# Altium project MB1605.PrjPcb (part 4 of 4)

## Sheet ETHERNET.SchDoc: ETHERNET
size A3; Date: Not used; ApprovedBy: Not used; CheckedBy: Not used; Author: Not used; CompanyName: STMicroelectronics; DrawnBy: Not used; Engineer: Not used; Organization: Not used; Address1: Not used; Address2: Not used; Address3: Not used; Address4: Not used; DocumentNumber: Not used; Revision: Not used; SheetNumber: 8; SheetTotal: 18
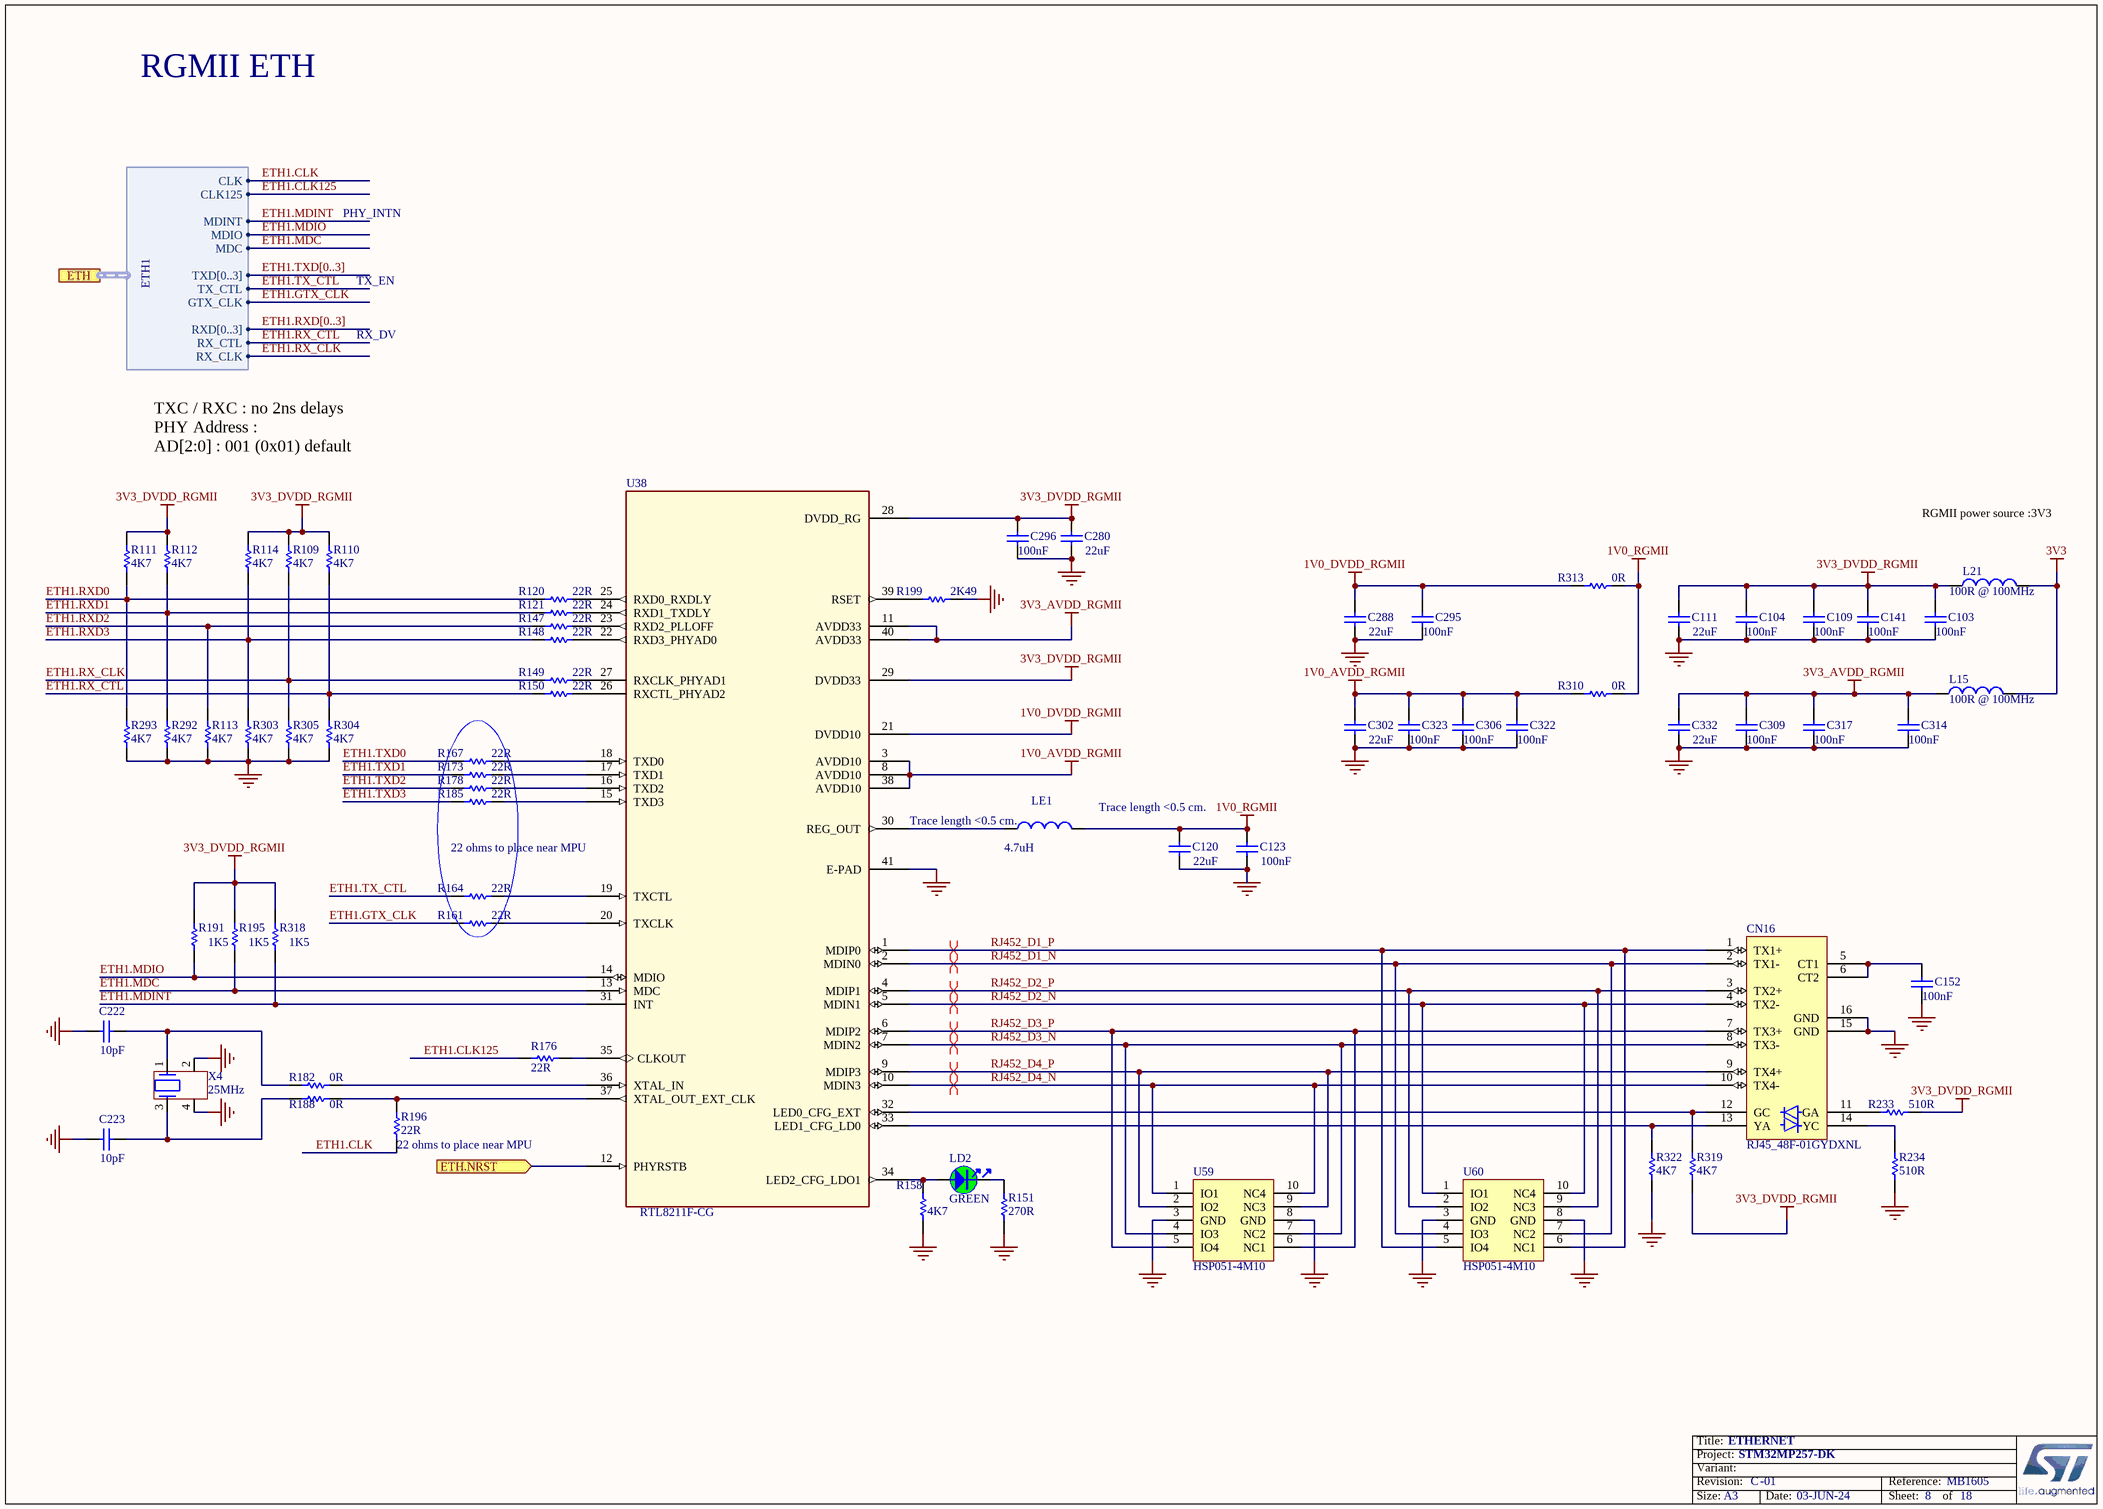
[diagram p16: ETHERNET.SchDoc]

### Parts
C103  value 100nF  [C0402]
C104  value 100nF  [C0402]
C109  value 100nF  [C0402]
C111  value 22uF  [C0603]
C120  value 22uF  [C0603]
C123  value 100nF  [C0402]
C141  value 100nF  [C0402]
C152  value 100nF  [C0402]
C222  value 10pF  [C0402]
C223  value 10pF  [C0402]
C280  value 22uF  [C0603]
C288  value 22uF  [C0603]
C295  value 100nF  [C0402]
C296  value 100nF  [C0402]
C302  value 22uF  [C0603]
C306  value 100nF  [C0402]
C309  value 100nF  [C0402]
C314  value 100nF  [C0402]
C317  value 100nF  [C0402]
C322  value 100nF  [C0402]
C323  value 100nF  [C0402]
C332  value 22uF  [C0603]
CN16  value RJ45_48F-01GYDXNL  [CON_RJ45_YD_48F-01GYDXNL_LED-P]  (hidden comment: ​New part for use of led pulled down on pin 13/14 , schematic more lisible.)
L15  value 100R @ 100MHz  [FIL_0603_H0P65]
L21  value 100R @ 100MHz  [FIL_0603_H0P65]
LD2  value GREEN  [LED_0603_OSRAM_LG-Q396-PS-35_GREEN_1A2K_H0P4]  (hidden comment: LED_green)
LE1  value 4.7uH  [L1210_LQH]
R109  value 4K7  [R0402]
R110  value 4K7  [R0402]
R111  value 4K7  [R0402]
R112  value 4K7  [R0402]
R113  value 4K7  [R0402]
R114  value 4K7  [R0402]
R120  value 22R  [R0201_H0P23]  (hidden comment: Resistor)
R121  value 22R  [R0201_H0P23]  (hidden comment: Resistor)
R147  value 22R  [R0201_H0P23]  (hidden comment: Resistor)
R148  value 22R  [R0201_H0P23]  (hidden comment: Resistor)
R149  value 22R  [R0201_H0P23]  (hidden comment: Resistor)
R150  value 22R  [R0201_H0P23]  (hidden comment: Resistor)
R151  value 270R  [R0402]  (hidden comment: Resistor)
R158  value 4K7  [R0402]
R161  value 22R  [R0201_H0P23]  (hidden comment: Resistor)
R164  value 22R  [R0201_H0P23]  (hidden comment: Resistor)
R167  value 22R  [R0201_H0P23]  (hidden comment: Resistor)
R173  value 22R  [R0201_H0P23]  (hidden comment: Resistor)
R176  value 22R  [R0201_H0P23]  (hidden comment: Resistor)
R178  value 22R  [R0201_H0P23]  (hidden comment: Resistor)
R182  value 0R  [R0402]
R185  value 22R  [R0201_H0P23]  (hidden comment: Resistor)
R188  value 0R  [R0402]
R191  value 1K5  [R0402]
R195  value 1K5  [R0402]
R196  value 22R  [R0201_H0P23]  (hidden comment: Resistor)
R199  value 2K49  [R0402]
R233  value 510R  [R0402]
R234  value 510R  [R0402]
R292  value 4K7  [R0402]
R293  value 4K7  [R0402]
R303  value 4K7  [R0402]
R304  value 4K7  [R0402]
R305  value 4K7  [R0402]
R310  value 0R  [R0603]
R313  value 0R  [R0603]
R318  value 1K5  [R0402]
R319  value 4K7  [R0402]
R322  value 4K7  [R0402]
U38  RTL8211F-CG  [ICC_QFN40-EPAD_5X5_P040]
U59  HSP051-4M10  [ESD_UQFN-10L_2P5X1_P050]
U60  HSP051-4M10  [ESD_UQFN-10L_2P5X1_P050]
X4  value 25MHz  [CRY_NX3225HA_4P]  (hidden comment: XTAL_4_PINS)

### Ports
ETH (harness ETH1), ETH.NRST (in)

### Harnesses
ETH1: MDINT, CLK125, TXD[0..3], MDIO, MDC, RX_CLK, GTX_CLK, TX_CTL, RXD[0..3], RX_CTL, CLK

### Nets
1V0_AVDD_RGMII: C302.2 C306.2 C322.2 C323.2 R310.1 U38.3(AVDD10) U38.8(AVDD10) U38.38(AVDD10)
1V0_DVDD_RGMII: C288.2 C295.2 R313.1 U38.21(DVDD10)
1V0_RGMII: C120.2 C123.2 LE1.2 R310.2 R313.2
3V3: L15.2 L21.2
3V3_AVDD_RGMII: C309.2 C314.2 C317.2 C332.2 L15.1 U38.11(AVDD33) U38.40(AVDD33)
3V3_DVDD_RGMII: C103.2 C104.2 C109.2 C111.2 C141.2 C280.1 C296.2 L21.1 R109.2 R110.2 R111.2 R112.2 R114.2 R191.2 R195.2 R233.2 R318.2 R319.1 U38.28(DVDD_RG) U38.29(DVDD33)
GND: C103.1 C104.1 C109.1 C111.1 C120.1 C123.1 C141.1 C152.1 C222.1 C223.1 C280.2 C288.1 C295.1 C296.1 C302.1 C306.1 C309.1 C314.1 C317.1 C322.1 C323.1 C332.1 CN16.15(GND) CN16.16(GND) R113.1 R151.2 R158.1 R199.2 R234.1 R292.1 R293.1 R303.1 R304.1 R305.1 R322.1 U38.41(E-PAD) U59.3(GND) U59.8(GND) U60.3(GND) U60.8(GND) X4.2 X4.4
ETH1.CLK: R196.1 ; port ETH.CLK
ETH1.CLK125: R176.1 ; port ETH.CLK125
ETH1.GTX_CLK: R161.1 ; port ETH.GTX_CLK
ETH1.MDC: R195.1 U38.13(MDC) ; port ETH.MDC
ETH1.MDINT: R318.1 U38.31(INT) ; port ETH.MDINT
ETH1.MDIO: R191.1 U38.14(MDIO) ; port ETH.MDIO
ETH1.NRST: U38.12(PHYRSTB) ; port ETH.NRST
ETH1.RX_CLK: R109.1 R149.1 R305.2 ; port ETH.RX_CLK
ETH1.RX_CTL: R110.1 R150.1 R304.2 ; port ETH.RX_CTL
ETH1.RXD0: R111.1 R120.1 R293.2
ETH1.RXD1: R112.1 R121.1 R292.2
ETH1.RXD2: R113.2 R147.1
ETH1.RXD3: R114.1 R148.1 R303.2
ETH1.TX_CTL: R164.1 ; port ETH.TX_CTL
ETH1.TXD0: R167.1
ETH1.TXD1: R173.1
ETH1.TXD2: R178.1
ETH1.TXD3: R185.1
RJ452_D1_N: CN16.2(TX1-) U38.2(MDIN0) U60.4(IO3) U60.7(NC2)
RJ452_D1_P: CN16.1(TX1+) U38.1(MDIP0) U60.5(IO4) U60.6(NC1)
RJ452_D2_N: CN16.4(TX2-) U38.5(MDIN1) U60.1(IO1) U60.10(NC4)
RJ452_D2_P: CN16.3(TX2+) U38.4(MDIP1) U60.2(IO2) U60.9(NC3)
RJ452_D3_N: CN16.8(TX3-) U38.7(MDIN2) U59.4(IO3) U59.7(NC2)
RJ452_D3_P: CN16.7(TX3+) U38.6(MDIP2) U59.5(IO4) U59.6(NC1)
RJ452_D4_N: CN16.10(TX4-) U38.10(MDIN3) U59.1(IO1) U59.10(NC4)
RJ452_D4_P: CN16.9(TX4+) U38.9(MDIP3) U59.2(IO2) U59.9(NC3)
NetC152_2: C152.2 CN16.5(CT1) CN16.6(CT2)
NetC222_2: C222.2 R182.1 X4.1
NetC223_2: C223.2 R188.1 X4.3
NetCN16_11: CN16.11(GA) R233.1
NetCN16_12: CN16.12(GC) R319.2 U38.32(LED0_CFG_EXT)
NetCN16_13: CN16.13(YA) R322.2 U38.33(LED1_CFG_LD0)
NetCN16_14: CN16.14(YC) R234.2
NetLD2_1: LD2.1 R158.2 U38.34(LED2_CFG_LDO1)
NetLD2_2: LD2.2 R151.1
NetLE1_1: LE1.1 U38.30(REG_OUT)
NetR120_2: R120.2 U38.25(RXD0_RXDLY)
NetR121_2: R121.2 U38.24(RXD1_TXDLY)
NetR147_2: R147.2 U38.23(RXD2_PLLOFF)
NetR148_2: R148.2 U38.22(RXD3_PHYAD0)
NetR149_2: R149.2 U38.27(RXCLK_PHYAD1)
NetR150_2: R150.2 U38.26(RXCTL_PHYAD2)
NetR161_2: R161.2 U38.20(TXCLK)
NetR164_2: R164.2 U38.19(TXCTL)
NetR167_2: R167.2 U38.18(TXD0)
NetR173_2: R173.2 U38.17(TXD1)
NetR176_2: R176.2 U38.35(CLKOUT)
NetR178_2: R178.2 U38.16(TXD2)
NetR182_2: R182.2 U38.36(XTAL_IN)
NetR185_2: R185.2 U38.15(TXD3)
NetR188_2: R188.2 R196.2 U38.37(XTAL_OUT_EXT_CLK)
NetR199_1: R199.1 U38.39(RSET)

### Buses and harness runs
bus ETH1.RXD[0..3]
bus ETH1.TXD[0..3]

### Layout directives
differential pair: RJ452_D1_N, RJ452_D1_P, RJ452_D2_N, RJ452_D2_P, RJ452_D3_N, RJ452_D3_P, RJ452_D4_N, RJ452_D4_P

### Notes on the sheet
- RGMII ETH
- PHY_INTN
- TX_EN
- RX_DV
- TXC / RXC : no 2ns delays
  PHY Address :
  AD[2:0] : 001 (0x01) default
- RGMII power source :3V3
- (near U38) 22 ohms to place near MPU
- (near LE1) Trace length <0.5 cm.
- Trace length <0.5 cm.
- (near R196) 22 ohms to place near MPU

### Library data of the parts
C103 C104 C109 C123 C141 C152 C295 C296 C306 C309 C314 C317 C322 C323 = MCD-00006: Capacitor,100nF,16V,X7R,10%,0402; Manufacturer_Part_Number: CC0402KRX7R7BB104; Manufacturer: YAGEO; Alternate_Manufacturer: MURATA; Alternate_Manufacturer_Part_Number: GCM155R71C104KA55D; Part_Preference: Recommended; Partial_Alternate_Internal_Part_Number: MCD-03299; Provided_By: SUBCO; Initial_Board_Reference: mb1274; Order_Code_RS: 616-9701; Alternate_EMS: M; Component_Country_Of_Origin: China; ID: 2474; ShowFields: YES
C111 C120 C280 C288 C302 C332 = MCD-00100: Capacitor,22uF,6V3,X5R,20%,0603; Manufacturer_Part_Number: GRM188R60J226MEA0J; Manufacturer: MURATA; Part_Preference: Recommended; ECCN_US: EAR99; ECCN_EU: NEC; Provided_By: SUBCO; Initial_Board_Reference: mb1262; Component_Country_Of_Origin: Japan; ID: 2766; ShowFields: YES
C222 C223 = MCD-00015: Capacitor,10pF,50V,NPO,5%,0402; Manufacturer_Part_Number: CC0402JRNPO9BN100; Manufacturer: YAGEO; Part_Preference: Recommended; Provided_By: SUBCO; Initial_Board_Reference: mb1274; Order_Code_RS: 616-9256; Component_Country_Of_Origin: China; ID: 2465; ShowFields: YES
CN16 = MCD-01129: Connector_RJ45, led pull down, T= 13.84mm; Manufacturer_Part_Number: 48F-01GYDXNL; Manufacturer: YUAN DEAN SCIENTIFIC; Part_Preference: Recommended; Component_Country_Of_Origin: Unknown; ID: 3367; ShowFields: YES
L15 L21 = MCD-00094: Ferrite bead 100R 2A 0603; Manufacturer_Part_Number: BLM18EG101TN1; Manufacturer: MURATA; Part_Type: Inductor; Part_Preference: Recommended; ECCN_US: EAR99; ECCN_EU: NEC; Provided_By: SUBCO; Initial_Board_Reference: mb1262; Order_Code_RS: 792-6246; Component_Country_Of_Origin: Japan; ID: 2774; ShowFields: YES
LD2 = MCD-00588: LED Green, 0603 SMD, Forward Voltage Typ=2V, Max=2.5V; Part_Type: Display; Manufacturer_Part_Number: LG Q396-PS-35; Manufacturer: OSRAM OPTO SEMICONDUCTORS; Alternate_Manufacturer_Part_Number: VLMTG1300-GS08; Alternate_Manufacturer: VISHAY SEMICONDUCTOR OPTO DIVISION; Alternate_Internal_Part_Number: MCD-02400; Part_Preference: Recommended; Provided_By: SUBCO; Component_Country_Of_Origin: Unknown; ID: 3155; ShowFields: YES
LE1 = MCD-00048: FIXED IND 4.7UH 1A 180 MOHM 30% SMD; Manufacturer_Part_Number: LQH32PN4R7NN0L; Manufacturer: MURATA; Part_Preference: Recommended; Provided_By: SUBCO; Initial_Board_Reference: mb1274; Order_Code_RS: 167-4086; Component_Country_Of_Origin: Japan; ID: 2544; ShowFields: YES
R109-R114 R292 R293 R303-R305 = MCD-00065: Resistor,4K7,0402,1%,1/16W; Manufacturer_Part_Number: RC0402FR-074K7L; Manufacturer: YAGEO; Alternate_Manufacturer_Part_Number: RT0402FRE074K7L; Part_Preference: Recommended; Partial_Alternate_Internal_Part_Number: MCD-03300; Provided_By: SUBCO; Initial_Board_Reference: mb1274; Component_Country_Of_Origin: China; ID: 2526; ShowFields: YES; Alternate_EMS: M
R120 R121 R147-R150 R161 R164 R167 R173 R176 R178 R185 R196 = MCD-02978: Resistor, 22R, 0201, +/-1%, 1/20W; Manufacturer_Part_Number: RC0201FR-0722RL; Manufacturer: YAGEO; Part_Preference: Recommended; Order_Code_RS: 198-7593; ID: 5094; ShowFields: YES; Component_Country_Of_Origin: China
R151 = MCD-00441: Resistor,270R,0402,1%,1/16W; Manufacturer_Part_Number: RC0402FR-07270RL; Manufacturer: YAGEO; Part_Preference: Recommended; Provided_By: SUBCO; ECCN_US: EAR99; ECCN_EU: NEC; Component_Country_Of_Origin: China; ID: 2838; ShowFields: YES
R158 R319 R322 = MCD-00065: Resistor,4K7,0402,1%,1/16W; Manufacturer_Part_Number: RC0402FR-074K7L; Manufacturer: YAGEO; Alternate_Manufacturer_Part_Number: RT0402FRE074K7L; Part_Preference: Recommended; Partial_Alternate_Internal_Part_Number: MCD-03300; Provided_By: SUBCO; Initial_Board_Reference: mb1274; Alternate_EMS: M; Component_Country_Of_Origin: China; ID: 2526; ShowFields: YES
R182 R188 = MCD-00052: Resistor,0R,0402,5%,1/16W; Manufacturer_Part_Number: RC0402JR-070RL; Manufacturer: YAGEO; Part_Preference: Recommended; Provided_By: SUBCO; Initial_Board_Reference: mb1274; Order_Code_RS: 618-5804; Component_Country_Of_Origin: China; ID: 2540; ShowFields: YES
R191 R195 R318 = MCD-00068: Resistor,1K5,0402,1%,1/16W; Manufacturer_Part_Number: RC0402FR-071K5L; Manufacturer: YAGEO; Part_Preference: Recommended; Provided_By: SUBCO; Initial_Board_Reference: mb1274; Component_Country_Of_Origin: China; ID: 2524; ShowFields: YES
R199 = MCD-00183: Resistor,2K49,0402,1%,1/16W; Manufacturer_Part_Number: RC0402FR-072K49L; Manufacturer: YAGEO; Part_Preference: Recommended; Provided_By: SUBCO; Component_Country_Of_Origin: China; ID: 2687; ShowFields: YES
R233 R234 = MCD-00064: Resistor,510R,0402,1%,1/16W; Manufacturer_Part_Number: RC0402FR-07510RL; Manufacturer: YAGEO; Part_Preference: Recommended; Provided_By: SUBCO; Initial_Board_Reference: mb1274; Component_Country_Of_Origin: China; ID: 2525; ShowFields: YES
R310 R313 = MCD-00056: Resistor,0R,0603,5%,1/10W; Manufacturer_Part_Number: RC0603JR-070RL; Manufacturer: YAGEO; Part_Preference: Recommended; Provided_By: SUBCO; Initial_Board_Reference: mb1274; Component_Country_Of_Origin: China; ID: 2536; ShowFields: YES
U38 = MCD-01130: 10/100/1000M GIGABIT Ethernet Transceiver, QFN40 , SMPS version; Manufacturer: REALTEK; Part_Type: IC; Part_Preference: Recommended; Provided_By: SUBCO; Initial_Board_Reference: MB1272; Component_Country_Of_Origin: Unknown; ID: 3370; ShowFields: YES
U59 U60 = MCD-00667: 4-line ESD protection for high speed lines; BMS_Part_Number: 9179041; Part_Type: Diode; Part_Preference: Recommended; Manufacturer: STMICROELECTRONICS; Manufacturer_HQ_COO: EU; Component_Country_Of_Origin: Philippines; ShowFields: YES; ID: 3081
X4 = MCD-01463: Crystal 25Mhz, 10pF, -+50PPM, SMD; Part_Type: Crystal_Osc; Manufacturer_Part_Number: NX3225GA-25MHZ-EXS00A-CG06750; Manufacturer: NDK; BMS_Part_Number: 9157035; Part_Preference: Recommended; Provided_By: SUBCO; Initial_Board_Reference: MB1272B; Remark: footprint same as CRY_NX3225HA_4P; Component_Country_Of_Origin: Unknown; ID: 3563; ShowFields: YES

## Sheet HDMI.SchDoc: HDMI
size A3; Date: 01-DEC-2013; CompanyName: STMicroelectronics; Organization: Microcontrollers Division; Address1: 12, Rue Jules HOROWITZ; Address2: 38019 Grenoble; Address3: FRANCE; DocumentNumber: MB1272; Revision: A-01; SheetNumber: 10; SheetTotal: 18; Project: STM32MP25-DISCO
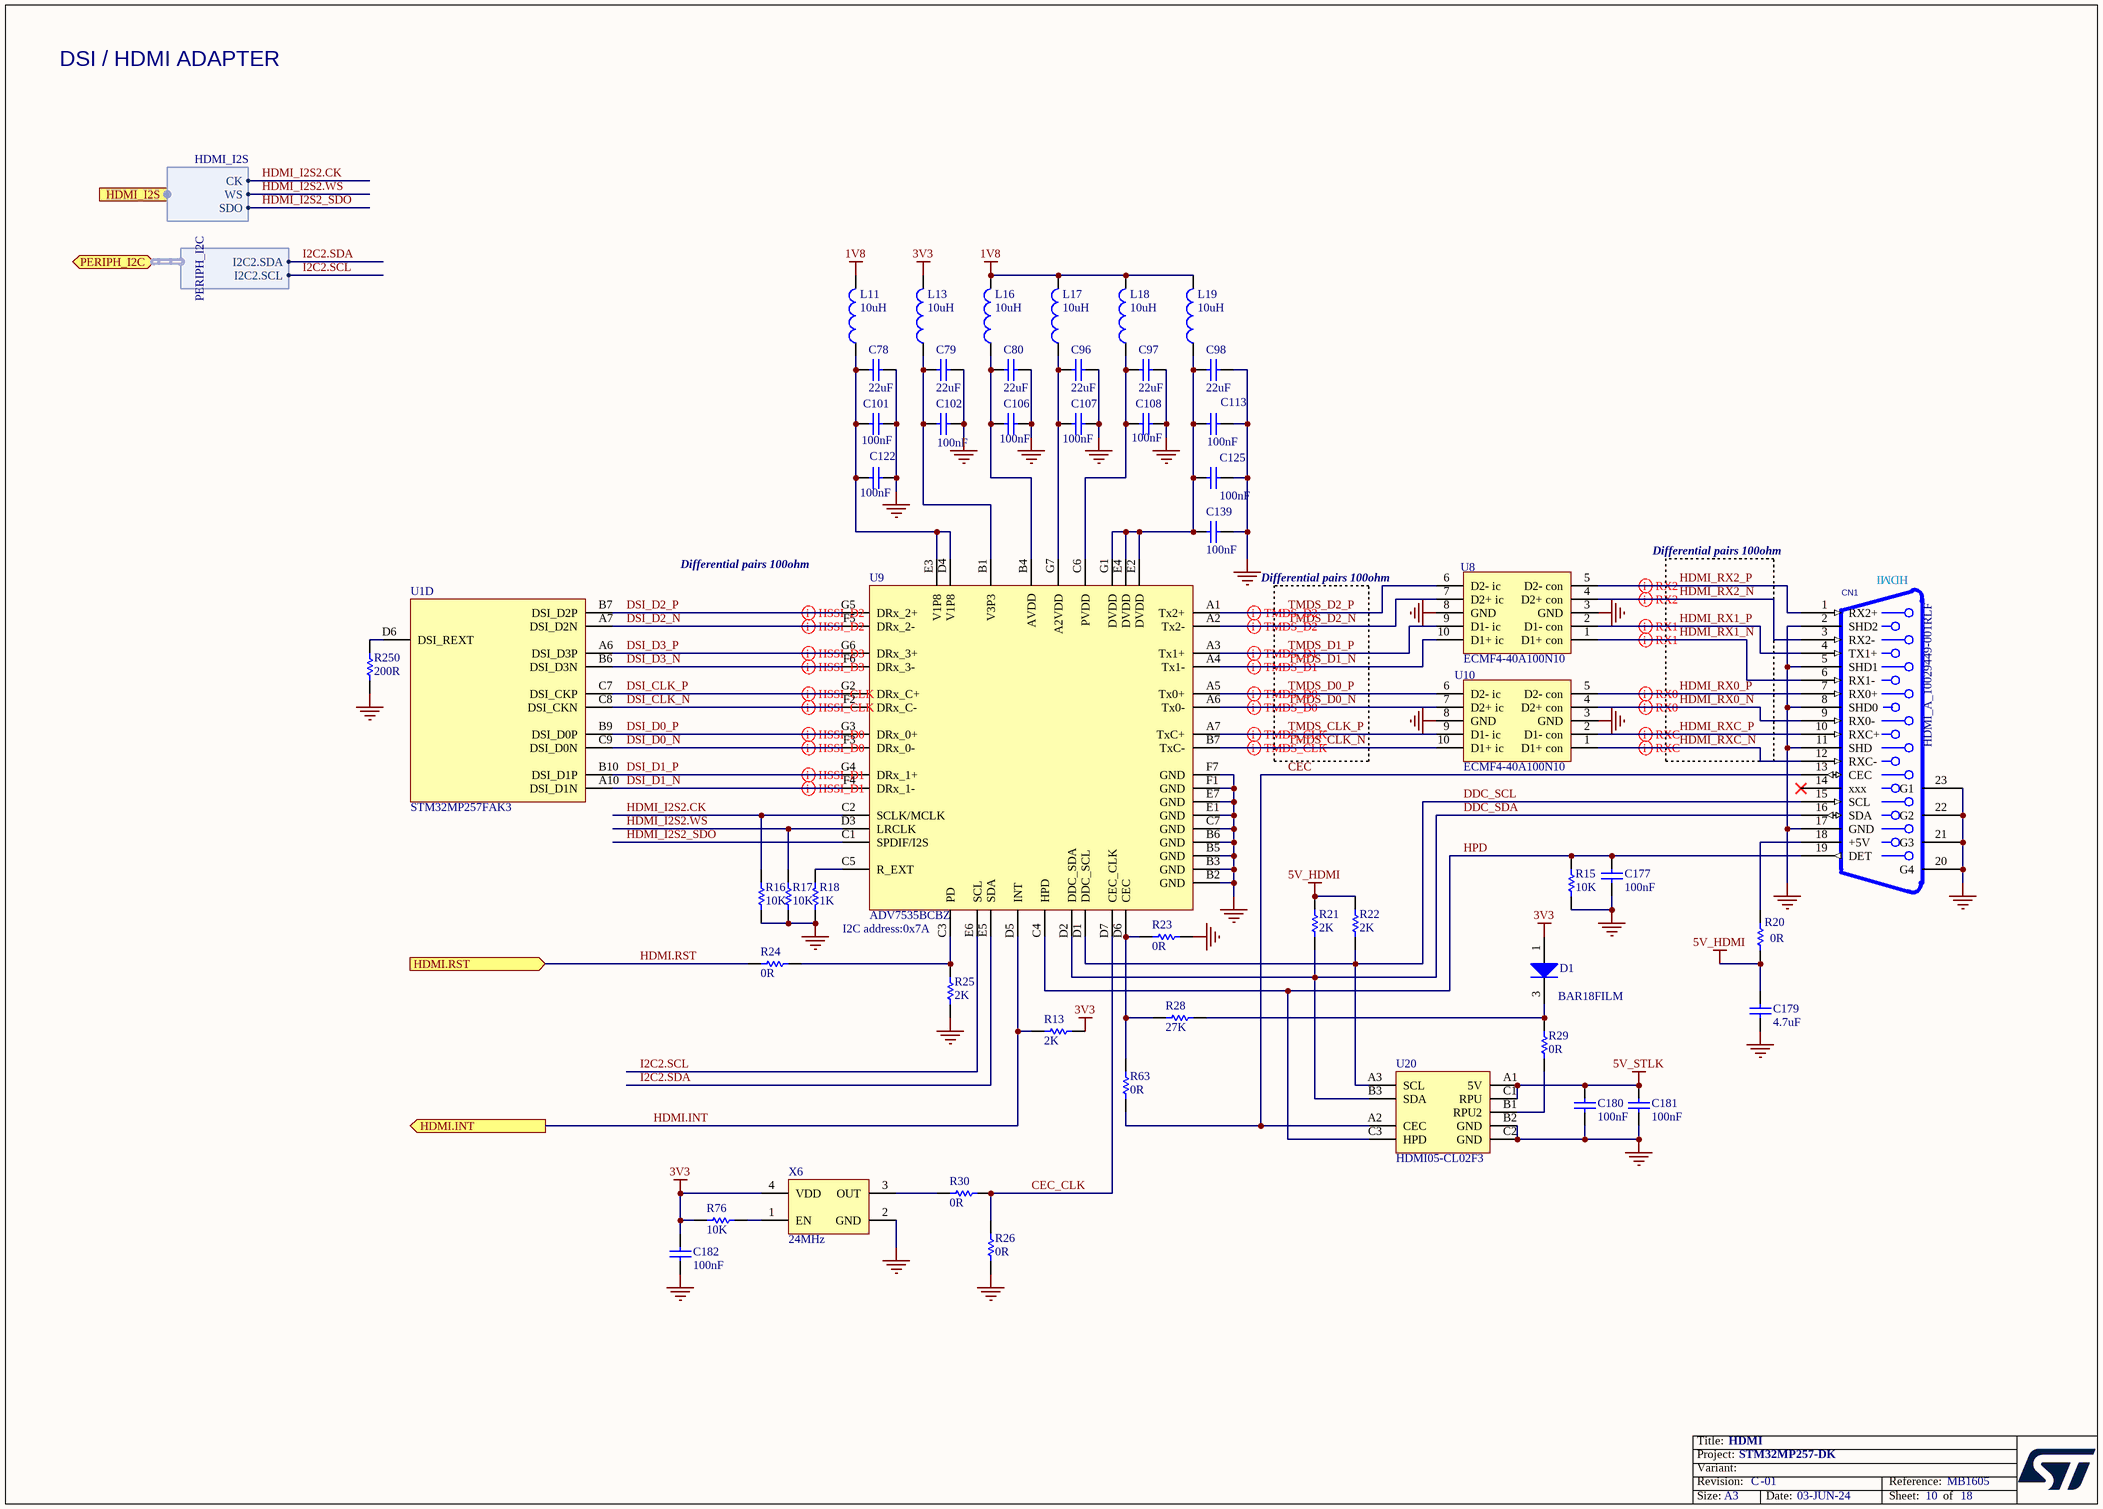
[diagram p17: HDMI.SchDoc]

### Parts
C78  value 22uF  [C0603]  (hidden comment: Capacitor)
C79  value 22uF  [C0603]  (hidden comment: Capacitor)
C80  value 22uF  [C0603]  (hidden comment: Capacitor)
C96  value 22uF  [C0603]  (hidden comment: Capacitor)
C97  value 22uF  [C0603]  (hidden comment: Capacitor)
C98  value 22uF  [C0603]  (hidden comment: Capacitor)
C101  value 100nF  [C0402]  (hidden comment: Capacitor)
C102  value 100nF  [C0402]  (hidden comment: Capacitor)
C106  value 100nF  [C0402]  (hidden comment: Capacitor)
C107  value 100nF  [C0402]  (hidden comment: Capacitor)
C108  value 100nF  [C0402]  (hidden comment: Capacitor)
C113  value 100nF  [C0402]  (hidden comment: Capacitor)
C122  value 100nF  [C0402]  (hidden comment: Capacitor)
C125  value 100nF  [C0402]  (hidden comment: Capacitor)
C139  value 100nF  [C0402]  (hidden comment: Capacitor)
C177  value 100nF  [C0402]  (hidden comment: Capacitor)
C179  value 4.7uF  [C0402]  (hidden comment: Capacitor)
C180  value 100nF  [C0402]  (hidden comment: Capacitor)
C181  value 100nF  [C0402]  (hidden comment: Capacitor)
C182  value 100nF  [C0402]  (hidden comment: Capacitor)
CN1  value HDMI_A_10029449-001RLF  [CON_HDMI_FCI-AMPHENOL_10029449-001RLF]  (hidden comment: HDMI_TypeA_DB19_7)
D1  value BAR18FILM  [DIO_SOT23_SC59_1A_2NC_3K_H1P4]  (hidden comment: DIODE_SOT23)
L11  value 10uH  [IND_0805_MURATA_LQM21]  (hidden comment: Inductor)
L13  value 10uH  [IND_0805_MURATA_LQM21]  (hidden comment: Inductor)
L16  value 10uH  [IND_0805_MURATA_LQM21]  (hidden comment: Inductor)
L17  value 10uH  [IND_0805_MURATA_LQM21]  (hidden comment: Inductor)
L18  value 10uH  [IND_0805_MURATA_LQM21]  (hidden comment: Inductor)
L19  value 10uH  [IND_0805_MURATA_LQM21]  (hidden comment: Inductor)
R13  value 2K  [R0402]  (hidden comment: Resistor)
R15  value 10K  [R0402]  (hidden comment: Resistor)
R16  value 10K  [R0402]  (hidden comment: Resistor)
R17  value 10K  [R0402]  (hidden comment: Resistor)
R18  value 1K  [R0402]  (hidden comment: Resistor)
R20  value 0R  [R0402]  (hidden comment: Resistor)
R21  value 2K  [R0402]  (hidden comment: Resistor)
R22  value 2K  [R0402]  (hidden comment: Resistor)
R23  value 0R  [R0402]  (hidden comment: Resistor)
R24  value 0R  [R0402]  (hidden comment: Resistor)
R25  value 2K  [R0402]  (hidden comment: Resistor)
R26  value 0R  [R0402]  (hidden comment: Resistor)
R28  value 27K  [R0603]  (hidden comment: Resistor)
R29  value 0R  [R0402]  (hidden comment: Resistor)
R30  value 0R  [R0402]  (hidden comment: Resistor)
R63  value 0R  [R0402]  (hidden comment: Resistor)
R76  value 10K  [R0402]  (hidden comment: Resistor)
R250  value 200R  [R0402]  (hidden comment: Resistor)
U1  STM32MP257FAK3  [ICC_TFBGA424_14X14_P050_H1P20_CODE-B0A2]  (part D of 9)
U8  ECMF4-40A100N10  [ESD_UQFN-10L_2P25X1P4_P040]
U9  ADV7535BCBZ  [ICC_WLCSP49_3P46X3P46_P050]
U10  ECMF4-40A100N10  [ESD_UQFN-10L_2P25X1P4_P040]
U20  HDMI05-CL02F3  [ESD_FLIP-CHIP_BGA9_1P14X1P14_P040]
X6  value 24MHz  [CRY_NZ2016SH_4P]  (hidden comment: OSCILLATOR_4_PINS)

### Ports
HDMI.INT (out), HDMI.RST (in), HDMI_I2S (harness HDMI_I2S), PERIPH_I2C (bidir, harness PERIPH_I2C)

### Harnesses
HDMI_I2S: CK, SDO, WS
PERIPH_I2C: I2C2.SDA, I2C2.SCL

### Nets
1V8: L11.2 L16.2 L17.2 L18.2 L19.2
3V3: C182.2 D1.1(A) L13.2 R13.1 R76.1 X6.4(VDD)
5V_HDMI: C179.2 R20.1 R21.2 R22.2
5V_STLK: C180.2 C181.2 U20.A1(5V) U20.C1(RPU)
GND: C78.2 C79.2 C80.2 C96.2 C97.2 C98.2 C101.1 C102.2 C106.2 C107.2 C108.1 C113.1 C122.1 C125.1 C139.1 C177.1 C179.1 C180.1 C181.1 C182.1 CN1.2(SHD2) CN1.5(SHD1) CN1.8(SHD0) CN1.11(SHD) CN1.17(GND) CN1.20(G4) CN1.21(G3) CN1.22(G2) CN1.23(G1) R15.2 R16.1 R17.1 R18.1 R23.2 R25.2 R26.1 R250.2 U8.3(GND) U8.8(GND) U9.B2(GND) U9.B3(GND) U9.B5(GND) U9.B6(GND) U9.C7(GND) U9.E1(GND) U9.E7(GND) U9.F1(GND) U9.F7(GND) U10.3(GND) U10.8(GND) U20.B2(GND) U20.C2(GND) X6.2(GND)
CEC: CN1.13(CEC) R63.1 U20.A2(CEC)
CEC_CLK: R26.2 R30.1 U9.D7(CEC_CLK)
DDC_SCL: CN1.15(SCL) R22.1 U9.D1(DDC_SCL) U20.A3(SCL)
DDC_SDA: CN1.16(SDA) R21.1 U9.D2(DDC_SDA) U20.B3(SDA)
DSI_CLK_N: U1.C8(DSI_CKN) U9.F2(DRx_C-)
DSI_CLK_P: U1.C7(DSI_CKP) U9.G2(DRx_C+)
DSI_D0_N: U1.C9(DSI_D0N) U9.F3(DRx_0-)
DSI_D0_P: U1.B9(DSI_D0P) U9.G3(DRx_0+)
DSI_D1_N: U1.A10(DSI_D1N) U9.F4(DRx_1-)
DSI_D1_P: U1.B10(DSI_D1P) U9.G4(DRx_1+)
DSI_D2_N: U1.A7(DSI_D2N) U9.F5(DRx_2-)
DSI_D2_P: U1.B7(DSI_D2P) U9.G5(DRx_2+)
DSI_D3_N: U1.B6(DSI_D3N) U9.F6(DRx_3-)
DSI_D3_P: U1.A6(DSI_D3P) U9.G6(DRx_3+)
HDMI.INT: R13.2 U9.D5(INT) ; port HDMI.INT
HDMI.RST: R24.1 ; port HDMI.RST
HDMI_I2S2.CK: R16.2 U9.C2(SCLK/MCLK) ; port HDMI_I2S.CK
HDMI_I2S2.WS: R17.2 U9.D3(LRCLK) ; port HDMI_I2S.WS
HDMI_I2S2_SDO: U9.C1(SPDIF/I2S) ; port HDMI_I2S.SDO
HDMI_RX0_N: CN1.9(RX0-) U10.4(D2+_con)
HDMI_RX0_P: CN1.7(RX0+) U10.5(D2-_con)
HDMI_RX1_N: CN1.6(RX1-) U8.1(D1+_con)
HDMI_RX1_P: CN1.4(TX1+) U8.2(D1-_con)
HDMI_RX2_N: CN1.3(RX2-) U8.4(D2+_con)
HDMI_RX2_P: CN1.1(RX2+) U8.5(D2-_con)
HDMI_RXC_N: CN1.12(RXC-) U10.1(D1+_con)
HDMI_RXC_P: CN1.10(RXC+) U10.2(D1-_con)
HPD: C177.2 CN1.19(DET) R15.1 U9.C4(HPD) U20.C3(HPD)
I2C2.SCL: U9.E6(SCL) ; port PERIPH_I2C.I2C2.SCL
I2C2.SDA: U9.E5(SDA) ; port PERIPH_I2C.I2C2.SDA
TMDS_CLK_N: U9.B7(TxC-) U10.10(D1+_ic)
TMDS_CLK_P: U9.A7(TxC+) U10.9(D1-_ic)
TMDS_D0_N: U9.A6(Tx0-) U10.7(D2+_ic)
TMDS_D0_P: U9.A5(Tx0+) U10.6(D2-_ic)
TMDS_D1_N: U8.10(D1+_ic) U9.A4(Tx1-)
TMDS_D1_P: U8.9(D1-_ic) U9.A3(Tx1+)
TMDS_D2_N: U8.7(D2+_ic) U9.A2(Tx2-)
TMDS_D2_P: U8.6(D2-_ic) U9.A1(Tx2+)
NetC78_1: C78.1 C101.2 C122.2 L11.1 U9.D4(V1P8) U9.E3(V1P8)
NetC79_1: C79.1 C102.1 L13.1 U9.B1(V3P3)
NetC80_1: C80.1 C106.1 L16.1 U9.B4(AVDD)
NetC96_1: C96.1 C107.1 L17.1 U9.G7(A2VDD)
NetC97_1: C97.1 C108.2 L18.1 U9.C6(PVDD)
NetC98_1: C98.1 C113.2 C125.2 C139.2 L19.1 U9.E2(DVDD) U9.E4(DVDD) U9.G1(DVDD)
NetCN1_18: CN1.18(+5V) R20.2
NetD1_3: D1.3(K) R28.1 R29.2
NetR18_2: R18.2 U9.C5(R_EXT)
NetR23_1: R23.1 R28.2 R63.2 U9.D6(CEC)
NetR24_2: R24.2 R25.1 U9.C3(PD)
NetR29_1: R29.1 U20.B1(RPU2)
NetR30_2: R30.2 X6.3(OUT)
NetR76_2: R76.2 X6.1(EN)
NetR250_1: R250.1 U1.D6(DSI_REXT)

Not connected (* = marked no-connect by the designer): CN1 14(xxx)*

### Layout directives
differential pair: DSI_CLK_N, DSI_CLK_P, DSI_D0_N, DSI_D0_P, DSI_D1_N, DSI_D1_P, DSI_D2_N, DSI_D2_P, DSI_D3_N, DSI_D3_P, HDMI_RX0_N, HDMI_RX0_P, HDMI_RX1_N, HDMI_RX1_P, HDMI_RX2_N, HDMI_RX2_P, HDMI_RXC_N, HDMI_RXC_P, TMDS_CLK_N, TMDS_CLK_P, TMDS_D0_N, TMDS_D0_P, TMDS_D1_N, TMDS_D1_P, TMDS_D2_N, TMDS_D2_P

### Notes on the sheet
- DSI / HDMI ADAPTER
- (near U9) Differential pairs 100ohm
- Differential pairs 100ohm
- (near CN1) HDMI
- (near U9) I2C address:0x7A

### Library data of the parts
C78-C80 C96-C98 = MCD-00100: Capacitor, MLCC, 22uF, 6V3, X5R, +/-20%, 0603, T=0.8mm; Part_Preference: Recommended; Manufacturer: MURATA; Manufacturer_Part_Number: GRM188R60J226MEA0J; Component_Country_Of_Origin: Japan; ShowFields: YES; ID: 2766
C101 C102 C106-C108 C113 C122 C125 C139 = MCD-00006: Capacitor, MLCC, 100nF, 16V, X7R, +/-10%, 0402, T=0.5mm; Part_Preference: Recommended; Manufacturer: YAGEO; Manufacturer_Part_Number: CC0402KRX7R7BB104; Partial_Alternate_Internal_Part_Number: MCD-03299; Order_Code_RS: 616-9701; Component_Country_Of_Origin: China; ShowFields: YES; ID: 2474; Alternate_EMS: M
C177 C180-C182 = MCD-00006: Capacitor, MLCC, 100nF, 16V, X7R, +/-10%, 0402, T=0.5mm; Part_Preference: Recommended; Manufacturer: YAGEO; Manufacturer_Part_Number: CC0402KRX7R7BB104; Partial_Alternate_Internal_Part_Number: MCD-03299; Order_Code_RS: 616-9701; Component_Country_Of_Origin: China; ID: 2474; ShowFields: YES; Alternate_EMS: M
C179 = MCD-01356: Capacitor, MLCC, 4.7uF, 6V3, X5R, +/-20%, 0402, T=0.5mm; Part_Preference: Recommended; Manufacturer: MURATA; Manufacturer_Part_Number: GRM155R60J475ME47; Order_Code_RS: 814-5230; Component_Country_Of_Origin: Japan; ShowFields: YES; ID: 3456
CN1 = MCD-00307: HDMI_Type A, Receptacle, 19x1, 0.5mm, VR, SMD, T= 6.1mm; Part_Type: Connector; Part_Preference: Recommended; Manufacturer: AMPHENOL ICC; Manufacturer_Part_Number: 10029449-001RLF; Order_Code_RS: 162-1999; Component_Country_Of_Origin: China; ShowFields: YES; ID: 2561
D1 = MCD-02333: Diode, Ultrafast and RF switching diode, VF=0.41V@IF=1mA, VBR=70V; Part_Preference: Recommended; Manufacturer: STMICROELECTRONICS; Order_Code_RS: 165-7525; Component_Country_Of_Origin: China; ShowFields: YES; ID: 4439
L11 L13 L16-L19 = MCD-02317: Inductor, 10uH, +/-20%, Isat 100mA, DCR 0.5Ohm,; Part_Preference: Recommended; Manufacturer: MURATA; Manufacturer_Part_Number: LQM21FN100M80L; Alternate_Manufacturer: TDK; Alternate_Manufacturer_Part_Number: MLZ2012M100WT000; Order_Code_RS: 786-7074; Component_Country_Of_Origin: Japan; ID: 4423; ShowFields: YES
R13 R21 R22 R25 = MCD-00419: Resistor, 2K, 0402, +/-1%, 1/16W; Part_Preference: Recommended; Manufacturer: YAGEO; Manufacturer_Part_Number: RC0402FR-072KL; Component_Country_Of_Origin: China; ID: 2861; ShowFields: YES
R15-R17 R76 = MCD-00053: Resistor, 10K, 0402, +/-1%, 1/16W; Part_Preference: Recommended; Manufacturer: YAGEO; Manufacturer_Part_Number: RC0402FR-0710KL; BMS_Part_Number: 9131590; Component_Country_Of_Origin: China; ID: 2539; ShowFields: YES
R18 = MCD-00061: Resistor, 1K, 0402, +/-1%,1/16W; Part_Preference: Recommended; Manufacturer: YAGEO; Manufacturer_Part_Number: RC0402FR-071KL; Component_Country_Of_Origin: China; ID: 2532; ShowFields: YES
R20 R23 R24 R26 R29 R30 R63 = MCD-00052: Resistor, 0R, 0402, +/-5%, 1/16W; Part_Preference: Recommended; Manufacturer: YAGEO; Manufacturer_Part_Number: RC0402JR-070RL; Order_Code_RS: 618-5804; Component_Country_Of_Origin: China; ShowFields: YES; ID: 2540
R28 = MCD-00444: Resistor, 27K, 0603, +/-1%, 1/10W; Part_Preference: Recommended; Manufacturer: YAGEO; Manufacturer_Part_Number: RC0603FR-0727KL; Component_Country_Of_Origin: China; ShowFields: YES; ID: 2833
R250 = MCD-00417: Resistor, 200R, 0402, +/-1%, 1/16W; Manufacturer_Part_Number: RC0402FR-07200RL; Manufacturer: YAGEO; Part_Preference: Recommended; Component_Country_Of_Origin: China; ID: 2860; ShowFields: YES
U1 = MCD-03375: MPU , 2xCortex-A35@1.5GHz, Cortex-M33@400MHz, TFBGA 14x14, pitch 0.5, 648KB SRAM, With Crypto; Part_Type: IC; Part_Preference: Recommended; Manufacturer: STMICROELECTRONICS; Component_Country_Of_Origin: Unknown; ShowFields: YES; ID: 5491
U8 U10 = MCD-03059: ESD protection & Common Filter High Speed serial Interfaces , 0.4 pitch; Part_Type: IC; Part_Preference: Recommended; Manufacturer: STMICROELECTRONICS; ShowFields: YES; ID: 5175; Component_Country_Of_Origin: China
U9 = MCD-02315: MIPI/DSI Receiver with HDMI Transmitter; Part_Type: IC; Part_Preference: Recommended; Manufacturer: ANALOG DEVICES; Component_Country_Of_Origin: Singapore; ShowFields: YES; ID: 4421
U20 = MCD-02316: 5-line HDMI control line ESD protection; Part_Type: IC; Part_Preference: Recommended; Manufacturer: STMICROELECTRONICS; Component_Country_Of_Origin: France; ShowFields: YES; ID: 4422
X6 = MCD-01627: Oscillator, SPXO, 24MHz, +/-50ppm, square wave, 3V3, 2x1.6mm; BMS_Part_Number: 9157051; Part_Type: Crystal_Osc; Part_Preference: Recommended; Manufacturer: NDK; Manufacturer_Part_Number: NZ2016SH-24MHZ-END4869F; Component_Country_Of_Origin: Unknown; ShowFields: YES; ID: 3727

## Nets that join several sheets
1V8: Power_PMIC (5 pins), Power_MPU (21 pins), SDcard_eMMC (11 pins), HDMI (5 pins)
3V3: WLAN_BLUETOOTH (10 pins), Peripherals (R136.1 R138.2 R142.2 R144.1), MP257_14x14 (R224.2 R228.2), Power_PMIC (8 pins), LVDS (C84.2 CN2.3 CN2.4 R3.1), USB_HUB (10 pins), USB3 (6 pins), CAMERA (C224.2 CN8.22), AUDIO (5 pins), Expansion_Connector (C232.1 CN5.1 CN5.17), ETHERNET (L15.2 L21.2), HDMI (6 pins)
5V_HDMI: Power_PMIC (C91.1 U26.7), HDMI (C179.2 R20.1 R21.2 R22.2)
5V_STLK: Power_PMIC (25 pins), LVDS (R4.2), STLINK_V3EC (7 pins), USB_HUB (C143.2 C146.2 L12.1), USB3 (C94.2 Q5.5 Q5.6), Expansion_Connector (C233.2 CN5.2 CN5.4), HDMI (C180.2 C181.2 U20.A1 U20.C1)
5V_VCONN: Power_PMIC (C214.1 U26.5), USB3 (5 pins)
GND: WLAN_BLUETOOTH (22 pins), Peripherals (17 pins), MP257_14x14 (9 pins), Power_PMIC (63 pins), Power_MPU (118 pins), LVDS (27 pins), STLINK_V3EC (105 pins), USB_HUB (36 pins), USB3 (44 pins), CAMERA (23 pins), AUDIO (5 pins), Expansion_Connector (10 pins), LPDDR4 (79 pins), SDcard_eMMC (30 pins), ETHERNET (42 pins), HDMI (53 pins)
VBAT: Peripherals (R139.2), Power_MPU (C87.2 D6.3 U1.T6)
VDD1_DDR: Power_PMIC (C40.2 U26.44), LPDDR4 (15 pins)
VDD2_DDR: Power_PMIC (5 pins), Power_MPU (14 pins), LPDDR4 (59 pins)
VDD3V3_USB: Power_PMIC (C61.2 U26.13), Power_MPU (R286.1)
VDD_EMMC: Power_PMIC (C190.1 U26.16), SDcard_eMMC (6 pins)
VDD_SDCARD: Power_PMIC (C215.1 U26.4), SDcard_eMMC (C218.2 CN6.4)
VDDA1V8_AON: MP257_14x14 (U1.W2), Power_PMIC (C189.2 U26.14), Power_MPU (C234.2 U1.AB3)
VDDCORE: Power_PMIC (6 pins), Power_MPU (24 pins)
VDDCPU: Power_PMIC (5 pins), Power_MPU (16 pins)
VDDGPU: Power_PMIC (6 pins), Power_MPU (18 pins)
VDDIO: Peripherals (9 pins), MP257_14x14 (9 pins), Power_PMIC (6 pins), Power_MPU (17 pins), STLINK_V3EC (LNK13.1), USB3 (R223.2)
VDDIO_SDCARD: Power_PMIC (C217.1 U26.2), Power_MPU (C195.2 U1.D14 U1.E13), SDcard_eMMC (7 pins)
BOOT0: Peripherals (SW1.1 TP15.1), MP257_14x14 (U1.Y3)
BOOT1: Peripherals (SW1.2 TP16.1), MP257_14x14 (U1.AA3)
BOOT2: Peripherals (SW2.1 TP25.1), MP257_14x14 (U1.AB1)
BOOT3: Peripherals (SW2.2 TP32.1), MP257_14x14 (U1.AB2)
BT_DEV_WAKE: WLAN_BLUETOOTH (U40.39), MP257_14x14 (U1.AE6)
BT_HOST_WAKE: WLAN_BLUETOOTH (U40.38), MP257_14x14 (U1.AG5)
BT_PCM_CLK: WLAN_BLUETOOTH (U40.11), MP257_14x14 (U1.T3)
BT_PCM_SDI: WLAN_BLUETOOTH (U40.10), MP257_14x14 (U1.P4)
BT_PCM_SDO: WLAN_BLUETOOTH (U40.9), MP257_14x14 (U1.K4)
BT_PCM_WS: WLAN_BLUETOOTH (U40.8), MP257_14x14 (U1.U2)
BT_REG_ON: WLAN_BLUETOOTH (TP19.1 U40.14), MP257_14x14 (U1.AD6)
BUTTON.TAMP: Peripherals (5 pins), MP257_14x14 (U1.W5)
BUTTON.USER1: Peripherals (C162.2 R127.1), MP257_14x14 (U1.AD10)
BUTTON.USER2: Peripherals (C161.2 R126.1), MP257_14x14 (U1.AD8)
CAM.EN: MP257_14x14 (U1.A11), CAMERA (CN8.18 U33.1)
CAM.IMU_INT1: MP257_14x14 (U1.F10), CAMERA (CN8.14 U31.1)
CAM.IMU_INT2: MP257_14x14 (U1.B11), CAMERA (CN8.15 U14.1)
CAM.RST: MP257_14x14 (U1.C12), CAMERA (CN8.17 U32.1)
CAM.TOF_INT: MP257_14x14 (U1.D8), CAMERA (CN8.12 U29.1)
CAM.TOF_LPn: MP257_14x14 (U1.C11), CAMERA (CN8.11 U11.1)
CTP.INT: MP257_14x14 (U1.J3), LVDS (CN2.2 U4.1)
CTP.RST: MP257_14x14 (U1.L7), LVDS (CN2.6 R3.2 U7.1)
DISP.BLCTRL: MP257_14x14 (U1.J5), LVDS (CN2.37 U23.1)
DISP.LED_EN: MP257_14x14 (U1.P6), LVDS (CN2.36 U22.1)
eMMC.SDMMC2_CK: MP257_14x14 (U1.B25), SDcard_eMMC (R103.1 U37.M6)
eMMC.SDMMC2_CMD: MP257_14x14 (U1.D24), SDcard_eMMC (R104.1 U37.M5)
eMMC.SDMMC2_D0: MP257_14x14 (U1.C24), SDcard_eMMC (R101.1 U37.A3)
eMMC.SDMMC2_D1: MP257_14x14 (U1.B23), SDcard_eMMC (U37.A4)
eMMC.SDMMC2_D2: MP257_14x14 (U1.C23), SDcard_eMMC (U37.A5)
eMMC.SDMMC2_D3: MP257_14x14 (U1.C25), SDcard_eMMC (U37.B2)
eMMC.SDMMC2_D4: MP257_14x14 (U1.D22), SDcard_eMMC (U37.B3)
eMMC.SDMMC2_D5: MP257_14x14 (U1.A23), SDcard_eMMC (U37.B4)
eMMC.SDMMC2_D6: MP257_14x14 (U1.A22), SDcard_eMMC (U37.B5)
eMMC.SDMMC2_D7: MP257_14x14 (U1.B22), SDcard_eMMC (U37.B6)
ETH1.CLK: MP257_14x14 (U1.AF11), ETHERNET (R196.1)
ETH1.CLK125: MP257_14x14 (U1.AA13), ETHERNET (R176.1)
ETH1.GTX_CLK: MP257_14x14 (U1.AB14), ETHERNET (R161.1)
ETH1.MDC: MP257_14x14 (U1.AF15), ETHERNET (R195.1 U38.13)
ETH1.MDINT: MP257_14x14 (U1.AC13), ETHERNET (R318.1 U38.31)
ETH1.MDIO: MP257_14x14 (U1.AE15), ETHERNET (R191.1 U38.14)
ETH1.NRST: MP257_14x14 (R205.1 U1.AF17), ETHERNET (U38.12)
ETH1.RX_CLK: MP257_14x14 (U1.AB12), ETHERNET (R109.1 R149.1 R305.2)
ETH1.RX_CTL: MP257_14x14 (U1.AD12), ETHERNET (R110.1 R150.1 R304.2)
ETH1.RXD0: MP257_14x14 (U1.AE11), ETHERNET (R111.1 R120.1 R293.2)
ETH1.RXD1: MP257_14x14 (U1.AE12), ETHERNET (R112.1 R121.1 R292.2)
ETH1.RXD2: MP257_14x14 (U1.AF13), ETHERNET (R113.2 R147.1)
ETH1.RXD3: MP257_14x14 (U1.AG13), ETHERNET (R114.1 R148.1 R303.2)
ETH1.TX_CTL: MP257_14x14 (U1.AD14), ETHERNET (R164.1)
ETH1.TXD0: MP257_14x14 (U1.AE13), ETHERNET (R167.1)
ETH1.TXD1: MP257_14x14 (U1.AG14), ETHERNET (R173.1)
ETH1.TXD2: MP257_14x14 (U1.AF14), ETHERNET (R178.1)
ETH1.TXD3: MP257_14x14 (U1.AE14), ETHERNET (R185.1)
EXP_GPIO2: MP257_14x14 (R246.1 U1.Y6), Expansion_Connector (CN5.3)
EXP_GPIO3: MP257_14x14 (R245.1 U1.V3), Expansion_Connector (CN5.5)
EXP_GPIO4: MP257_14x14 (TP11.1 U1.AE4), Expansion_Connector (CN5.7)
EXP_GPIO5: MP257_14x14 (U1.AG10), Expansion_Connector (CN5.29)
EXP_GPIO6: MP257_14x14 (U1.AD16), Expansion_Connector (CN5.31)
EXP_GPIO7: MP257_14x14 (U1.R5), Expansion_Connector (CN5.26)
EXP_GPIO8: MP257_14x14 (U1.AF10), Expansion_Connector (CN5.24)
EXP_GPIO9: MP257_14x14 (U1.AC9), Expansion_Connector (CN5.21)
EXP_GPIO10: MP257_14x14 (U1.AF9), Expansion_Connector (CN5.19)
EXP_GPIO11: MP257_14x14 (U1.AB8), Expansion_Connector (CN5.23)
EXP_GPIO12: MP257_14x14 (U1.AE17), Expansion_Connector (CN5.32)
EXP_GPIO13: MP257_14x14 (U1.AC19), Expansion_Connector (CN5.33)
EXP_GPIO14: MP257_14x14 (U1.P2), Expansion_Connector (CN5.8)
EXP_GPIO15: MP257_14x14 (U1.P3), Expansion_Connector (CN5.10)
EXP_GPIO16: MP257_14x14 (U1.R2), Expansion_Connector (CN5.36)
EXP_GPIO17: MP257_14x14 (U1.R3), Expansion_Connector (CN5.11)
EXP_GPIO18: MP257_14x14 (U1.D12), Expansion_Connector (CN5.12)
EXP_GPIO19: MP257_14x14 (U1.B17), Expansion_Connector (CN5.35)
EXP_GPIO20: MP257_14x14 (U1.A19), Expansion_Connector (CN5.38)
EXP_GPIO21: MP257_14x14 (U1.C14), Expansion_Connector (CN5.40)
EXP_GPIO22: MP257_14x14 (U1.T4), Expansion_Connector (CN5.15)
EXP_GPIO23: MP257_14x14 (U1.U7), Expansion_Connector (CN5.16)
EXP_GPIO24: MP257_14x14 (U1.V4), Expansion_Connector (CN5.18)
EXP_GPIO25: MP257_14x14 (U1.V2), Expansion_Connector (CN5.22)
EXP_GPIO26: MP257_14x14 (U1.V1), Expansion_Connector (CN5.37)
EXP_GPIO27: MP257_14x14 (U1.U3), Expansion_Connector (CN5.13)
HDMI.INT: MP257_14x14 (U1.B15), HDMI (R13.2 U9.D5)
HDMI.RST: MP257_14x14 (U1.C13), HDMI (R24.1)
HDMI_I2S2.CK: MP257_14x14 (U1.B13), HDMI (R16.2 U9.C2)
HDMI_I2S2.WS: MP257_14x14 (U1.B14), HDMI (R17.2 U9.D3)
HDMI_I2S2_SDO: MP257_14x14 (U1.A14), HDMI (U9.C1)
I2C1.SCL: MP257_14x14 (R224.1 U1.P1), USB3 (U50.18)
I2C1.SDA: MP257_14x14 (R228.1 U1.M6), USB3 (U50.17)
I2C2.SCL: MP257_14x14 (R32.1 U1.AC15), LVDS (CN2.7 U13.1), USB_HUB (SB1.1), CAMERA (CN8.20 U19.1), Expansion_Connector (CN5.28), HDMI (U9.E6)
I2C2.SDA: MP257_14x14 (R31.1 U1.AA15), LVDS (CN2.8 U3.1), USB_HUB (SB2.1), CAMERA (CN8.21 U39.1), Expansion_Connector (CN5.27), HDMI (U9.E5)
I2C7.SCL: MP257_14x14 (R261.1 U1.E15), Power_PMIC (U26.33)
I2C7.SDA: MP257_14x14 (R260.1 U1.E19), Power_PMIC (U26.34)
JTCK_SWCLK: MP257_14x14 (TP43.1 U1.AA5), STLINK_V3EC (R153.2)
JTDI: MP257_14x14 (TP41.1 U1.AE3), STLINK_V3EC (R207.2)
JTDO_SWDO: MP257_14x14 (TP13.1 U1.AC2), STLINK_V3EC (R129.2)
JTMS_SWDIO: MP257_14x14 (TP40.1 U1.AE2), STLINK_V3EC (R209.2)
LED1: Peripherals (LD7.2), MP257_14x14 (U1.AB16)
LED2: Peripherals (Q3.1 R137.2), MP257_14x14 (U1.AG18)
LED3: Peripherals (Q2.1 R141.2), MP257_14x14 (U1.AF19)
LED4: Peripherals (Q1.1 R143.2), MP257_14x14 (U1.AE16)
LPO_32: WLAN_BLUETOOTH (TP17.1 U40.37), MP257_14x14 (U1.U5)
MDF.CCK: MP257_14x14 (U1.AE18), AUDIO (U12.3 U53.3)
MDF.SDI6: MP257_14x14 (U1.AF18), AUDIO (U12.4 U53.4)
MP257_WAKEUP: MP257_14x14 (U1.AF5), Power_PMIC (U26.32)
NRST: Peripherals (B1.1 R33.1 TP22.1 U15.1), MP257_14x14 (C33.2 U1.AE1), Power_PMIC (R81.1), STLINK_V3EC (R212.2)
NRSTC1MS: MP257_14x14 (R27.1 R272.1 U1.W3), Power_PMIC (R59.1), SDcard_eMMC (D7.2)
PMIC_WAKEUPn: MP257_14x14 (U1.W7), Power_PMIC (R46.1)
PWR_CPU_ON: MP257_14x14 (R272.2 U1.AB4), Power_PMIC (R60.1)
PWR_ON: MP257_14x14 (U1.AD3), Power_PMIC (R61.1)
SD.SDMMC1_CK: MP257_14x14 (U1.C21), SDcard_eMMC (R9.1)
SD.SDMMC1_CMD: MP257_14x14 (U1.C20), SDcard_eMMC (CN6.3 R37.1 U5.4 U5.7)
SD.SDMMC1_D0: MP257_14x14 (U1.B21), SDcard_eMMC (CN6.7 R38.1 U6.2 U6.9)
SD.SDMMC1_D1: MP257_14x14 (U1.C22), SDcard_eMMC (CN6.8 R39.1 U6.4 U6.7)
SD.SDMMC1_D2: MP257_14x14 (U1.B19), SDcard_eMMC (CN6.1 R35.1 U5.1 U5.10)
SD.SDMMC1_D3: MP257_14x14 (U1.C19), SDcard_eMMC (CN6.2 R36.1 U5.2 U5.9)
SD.uSD_DETECT: MP257_14x14 (U1.G13), SDcard_eMMC (R40.1)
TCPP_EN: MP257_14x14 (U1.AD18), USB3 (R10.1)
TCPP_INTN: MP257_14x14 (U1.AD4), USB3 (U50.19)
USART1_CTS: WLAN_BLUETOOTH (U40.5), MP257_14x14 (U1.N7)
USART1_RTS: WLAN_BLUETOOTH (U40.4), MP257_14x14 (U1.N5)
USART1_RX: WLAN_BLUETOOTH (TP9.1 U40.3), MP257_14x14 (U1.K6)
USART1_TX: WLAN_BLUETOOTH (TP1.1 U40.2), MP257_14x14 (U1.N1)
USBH_N: USB_HUB (U34.19), USB3 (U1.AG21)
USBH_P: USB_HUB (U34.20), USB3 (U1.AF21)
USBSW_OE: MP257_14x14 (U1.AC17), USB3 (R105.1 U56.7)
USBSW_S: MP257_14x14 (U1.AE19), USB3 (R106.2 U56.6)
VBUS_DIV: MP257_14x14 (TP35.1 U1.AE5), USB3 (C99.1 R219.1 R220.2)
VCONN_CC1_EN: MP257_14x14 (U1.AA11), USB3 (Q11.1 R41.2)
VCONN_CC2_EN: MP257_14x14 (U1.AA9), USB3 (Q12.1 R200.2)
WL.SDMMC3_CK: WLAN_BLUETOOTH (TP10.1 U40.20), MP257_14x14 (U1.A26)
WL.SDMMC3_CMD: WLAN_BLUETOOTH (R93.2 U40.22), MP257_14x14 (U1.B26)
WL.SDMMC3_D0: WLAN_BLUETOOTH (R92.2 U40.24), MP257_14x14 (U1.C27)
WL.SDMMC3_D1: WLAN_BLUETOOTH (R91.2 U40.26), MP257_14x14 (U1.D25)
WL.SDMMC3_D2: WLAN_BLUETOOTH (R90.2 U40.23), MP257_14x14 (U1.C26)
WL.SDMMC3_D3: WLAN_BLUETOOTH (R89.2 U40.25), MP257_14x14 (U1.B27)
WL_HOST_WAKE: WLAN_BLUETOOTH (U40.27), MP257_14x14 (U1.N2)
WL_REG_ON: WLAN_BLUETOOTH (TP18.1 U40.28), MP257_14x14 (U1.L5)

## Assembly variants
MP257F: not fitted C25 C165 C166 C167 C174 C175 C176 CN14 D7 R16 R17 R23 R25 R26 R27 R29 R94 R95 R109 R110 R111 R112 R139 R196 R223 R227 R229 R303 R325 SB1 SB2 U49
